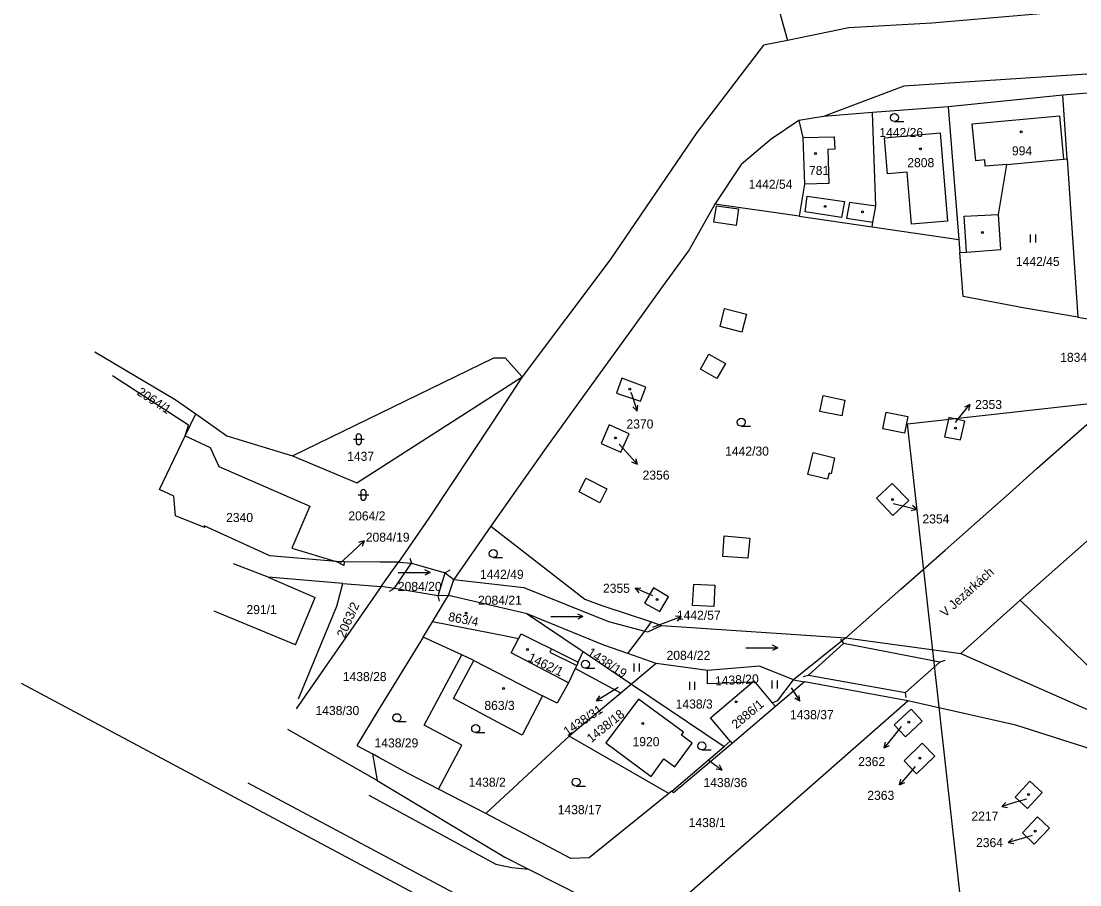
# Model space of a CAD drawing. Extents: x -793666 to -785424, y -1118958 to -1108761.
# Drawn here: x -792987.4 to -792788.6, y -1110324.4 to -1110162.1 of the extents above; entities that cross this region are included whole.
import ezdxf

# ---------------------------------------------------------------- set-up
doc = ezdxf.new("R2010")
doc.units = 0
for name, color, linetype in [('1_2000 - úřady', 7, 'Continuous'), ('Hranice parcel', 7, 'Continuous'), ('Parcelní čísla', 7, 'Continuous'), ('Pop  PČ popisy', 7, 'Continuous'), ('Vnitřní kresba', 7, 'Continuous'), ('Značky budov', 7, 'Continuous'), ('Značky kultur', 7, 'Continuous')]:
    doc.layers.add(name, color=color, linetype=linetype)

msp = doc.modelspace()

# ---------------------------------------------------------------- linework, layer by layer
at = {"layer": '1_2000 - úřady'}
msp.add_lwpolyline([(-792522.06, -1110204.41), (-792422.02, -1111099.6), (-792720.93, -1111133), (-792820.96, -1110237.81)], close=True, dxfattribs=at)
at = {"layer": 'Hranice parcel'}
for p, q in [((-792845.9, -1110157.04), (-792843.51, -1110165.75)), ((-792765.3, -1110173.93), (-792791.78, -1110176.05)), ((-792791.78, -1110176.05), (-792813.29, -1110178.21)), ((-792790.97, -1110188.03), (-792791.78, -1110176.05)), ((-792813.29, -1110178.21), (-792827.55, -1110179.32)), ((-792813.29, -1110178.21), (-792811.29, -1110203.16)), ((-792836.73, -1110180.03), (-792841.38, -1110180.79)), ((-792827.55, -1110179.32), (-792836.73, -1110180.03)), ((-792790.97, -1110188.03), (-792788.97, -1110217.76)), ((-792841.32, -1110198.79), (-792857.15, -1110196.49)), ((-792841.32, -1110198.79), (-792827.6, -1110200.79)), ((-792827.6, -1110200.79), (-792811.29, -1110203.16)), ((-792811.29, -1110203.16), (-792811.1, -1110205.6)), ((-792788.97, -1110217.76), (-792768.39, -1110221.23)), ((-792973.54, -1110224.23), (-792958.48, -1110233.18)), ((-792958.48, -1110233.18), (-792954.6, -1110235.91)), ((-792956.62, -1110240.06), (-792954.6, -1110235.91)), ((-792954.6, -1110235.91), (-792948.79, -1110240.01)), ((-792956.62, -1110240.06), (-792951.92, -1110242.23)), ((-792948.79, -1110240.01), (-792936.43, -1110243.76)), ((-792769.54, -1110244.05), (-792799.79, -1110270.88)), ((-792899.17, -1110257.02), (-792906.12, -1110267.05)), ((-792926.76, -1110263.67), (-792928.23, -1110263.66)), ((-792919.79, -1110268.32), (-792916.57, -1110263.77)), ((-792919.79, -1110268.32), (-792935.78, -1110291.3)), ((-792907.12, -1110270), (-792906.12, -1110267.05)), ((-792892.36, -1110273.46), (-792907.12, -1110270)), ((-792810.95, -1110280.9), (-792799.79, -1110270.88)), ((-792911.93, -1110277.84), (-792910.16, -1110274.96)), ((-792870.31, -1110276.7), (-792869.04, -1110275)), ((-792869.04, -1110275), (-792867.13, -1110275.64)), ((-792867.13, -1110275.64), (-792832.52, -1110277.99)), ((-792904.66, -1110281.18), (-792911.93, -1110277.84)), ((-792873.47, -1110280.93), (-792870.31, -1110276.7)), ((-792832.52, -1110277.99), (-792842.37, -1110285.86)), ((-792832.52, -1110277.99), (-792810.95, -1110280.9)), ((-792882.78, -1110282.53), (-792881.86, -1110280.55)), ((-792881.86, -1110280.55), (-792872.78, -1110286.68)), ((-792868.13, -1110282.78), (-792873.47, -1110280.93)), ((-792883.35, -1110283.75), (-792884.61, -1110286.45)), ((-792874.76, -1110288.34), (-792883.35, -1110283.75)), ((-792868.13, -1110282.78), (-792872.78, -1110286.68)), ((-792858.5, -1110284.12), (-792868.13, -1110282.78)), ((-792840.31, -1110286.24), (-792845.77, -1110290.89)), ((-792842.37, -1110285.86), (-792840.31, -1110286.24)), ((-792820.87, -1110289.8), (-792840.31, -1110286.24)), ((-792874.76, -1110288.34), (-792884.46, -1110296.46)), ((-792872.78, -1110286.68), (-792874.76, -1110288.34)), ((-792872.78, -1110286.68), (-792855.41, -1110298.4)), ((-792845.77, -1110290.89), (-792846.34, -1110290.21)), ((-792845.77, -1110290.89), (-792853.89, -1110297.81)), ((-792920.52, -1110304.75), (-792937.34, -1110295.19)), ((-792884.46, -1110296.46), (-792900.15, -1110310.99)), ((-792865.76, -1110307.22), (-792884.46, -1110296.46)), ((-792924.39, -1110298.18), (-792921.42, -1110299.79)), ((-792865.22, -1110306.76), (-792855.41, -1110298.4)), ((-792853.89, -1110297.81), (-792864.87, -1110307.09)), ((-792855.41, -1110298.4), (-792854.27, -1110297.36)), ((-792854.27, -1110297.36), (-792853.89, -1110297.81)), ((-792921.42, -1110299.79), (-792920.52, -1110304.75)), ((-792900.15, -1110310.99), (-792909.06, -1110306.37)), ((-792865.22, -1110306.76), (-792865.76, -1110307.22)), ((-792864.87, -1110307.09), (-792865.22, -1110306.76))]:
    msp.add_line(p, q, dxfattribs=at)
for points in [[(-792793.11, -1110160.53), (-792816.41, -1110162.52), (-792831.95, -1110163.4), (-792843.51, -1110165.75)], [(-792843.51, -1110165.75), (-792848, -1110166.66), (-792860.5, -1110183.08), (-792876.83, -1110207.04), (-792893.29, -1110228.94)], [(-792724.21, -1110167.98), (-792821.65, -1110174.35), (-792836.73, -1110180.03)], [(-792841.38, -1110180.79), (-792846.53, -1110184.28), (-792852.19, -1110189.06), (-792857.15, -1110196.49)], [(-792841.38, -1110180.79), (-792840.6, -1110183.99), (-792840.3, -1110192.79), (-792841.32, -1110198.79)], [(-792827.6, -1110200.79), (-792827.45, -1110199.93), (-792826.92, -1110196.88), (-792827.55, -1110179.32)], [(-792813.45, -1110199.69), (-792820.2, -1110200.26), (-792821.03, -1110190.53), (-792824.71, -1110190.8), (-792825.3, -1110184.04), (-792814.83, -1110183.14), (-792813.45, -1110199.69)], [(-792811.1, -1110205.6), (-792809.89, -1110205.52), (-792803.4, -1110205.05), (-792803.88, -1110198.43), (-792802.3, -1110189.05), (-792791.66, -1110188.09), (-792790.97, -1110188.03)], [(-792857.15, -1110196.49), (-792861.96, -1110205.07), (-792867.33, -1110212.5), (-792872.43, -1110219.57), (-792877.35, -1110226.4), (-792878.15, -1110227.5), (-792883.23, -1110234.55), (-792888.74, -1110242.19), (-792893.98, -1110249.64), (-792899.17, -1110257.02)], [(-792788.97, -1110217.76), (-792798.95, -1110216.07), (-792810.47, -1110213.88), (-792811.1, -1110205.6)], [(-792832.52, -1110277.99), (-792822.21, -1110268.85), (-792813.91, -1110261.49), (-792801.89, -1110250.87), (-792796.66, -1110246.15), (-792768.39, -1110221.23)], [(-792936.43, -1110243.76), (-792898.61, -1110225.41), (-792896.52, -1110225.36), (-792893.29, -1110228.94)], [(-792956.62, -1110240.06), (-792955.98, -1110238.02), (-792970.23, -1110228.78)], [(-792936.43, -1110243.76), (-792924.34, -1110248.84), (-792893.29, -1110228.94)], [(-792893.29, -1110228.94), (-792898.91, -1110237.46), (-792910.83, -1110255.53), (-792916.57, -1110263.77)], [(-792874.62, -1110229.22), (-792875.6, -1110231.99), (-792871.07, -1110233.51), (-792870.1, -1110230.91), (-792874.62, -1110229.22)], [(-792813.99, -1110240.21), (-792811, -1110240.77), (-792810.21, -1110237.29), (-792813.21, -1110236.61), (-792813.99, -1110240.21)], [(-792874.8, -1110243.12), (-792873.23, -1110239.68), (-792876.98, -1110237.97), (-792878.45, -1110241.45), (-792874.8, -1110243.12)], [(-792928.23, -1110263.66), (-792940.73, -1110262.6), (-792953.02, -1110256.95), (-792953, -1110257.24), (-792958.43, -1110255.07), (-792958.74, -1110251.34), (-792961.42, -1110250.11), (-792956.62, -1110240.06)], [(-792951.92, -1110242.23), (-792950.31, -1110245.78), (-792933.18, -1110253.25), (-792936.55, -1110261.13), (-792928.23, -1110263.66)], [(-792823.85, -1110248.99), (-792826.77, -1110251.75), (-792823.7, -1110254.99), (-792820.68, -1110252.18), (-792823.85, -1110248.99)], [(-792899.17, -1110257.02), (-792881.53, -1110270.73), (-792878.38, -1110271.88), (-792869.04, -1110275)], [(-792927.02, -1110267.74), (-792941.03, -1110266.61), (-792947.55, -1110264.05)], [(-792926.76, -1110263.67), (-792926.8, -1110264.36), (-792928.23, -1110263.66)], [(-792916.57, -1110263.77), (-792919.91, -1110263.74), (-792926.76, -1110263.67)], [(-792916.57, -1110263.77), (-792914.11, -1110263.94), (-792907.75, -1110265.75), (-792906.12, -1110267.05)], [(-792935.32, -1110289.46), (-792928.14, -1110272.02), (-792927.02, -1110267.74)], [(-792927.02, -1110267.74), (-792921.4, -1110268.19), (-792919.79, -1110268.32)], [(-792907.12, -1110270), (-792909.08, -1110270.11), (-792917.38, -1110268.7), (-792919.79, -1110268.32)], [(-792906.12, -1110267.05), (-792893, -1110268.51), (-792877.11, -1110274.91), (-792870.31, -1110276.7)], [(-792867.49, -1110273.06), (-792865.84, -1110270.25), (-792868.65, -1110268.61), (-792870.36, -1110271.49), (-792867.49, -1110273.06)], [(-792910.16, -1110274.96), (-792907.69, -1110270.93), (-792907.12, -1110270)], [(-792799.79, -1110270.88), (-792785.68, -1110284.61), (-792780.46, -1110289.67), (-792774.1, -1110287.81), (-792768.98, -1110283.36), (-792748.68, -1110294.88)], [(-792892.36, -1110273.46), (-792882.45, -1110280.15), (-792881.86, -1110280.55)], [(-792873.47, -1110280.93), (-792877.98, -1110279.37), (-792892.36, -1110273.46)], [(-792894.02, -1110278.16), (-792896.04, -1110277.71), (-792910.16, -1110274.96)], [(-792870.31, -1110276.7), (-792869.7, -1110276.86), (-792867.13, -1110275.64)], [(-792911.93, -1110277.84), (-792920.4, -1110291.66), (-792924.39, -1110298.18)], [(-792884.61, -1110286.45), (-792895.4, -1110280.77), (-792894.02, -1110278.16)], [(-792894.02, -1110278.16), (-792893.53, -1110277.23), (-792890.72, -1110278.62), (-792887.81, -1110280.05), (-792882.78, -1110282.53)], [(-792909.06, -1110306.37), (-792904.65, -1110298.12), (-792911.69, -1110294.36), (-792904.66, -1110281.18)], [(-792884.61, -1110286.45), (-792886.72, -1110290.26), (-792889.5, -1110288.84), (-792893.29, -1110296.28), (-792896.99, -1110294.3), (-792906.21, -1110289.36), (-792902.39, -1110282.23), (-792904.66, -1110281.18)], [(-792882.78, -1110282.53), (-792883.08, -1110283.17), (-792883.35, -1110283.75)], [(-792810.95, -1110280.9), (-792780.07, -1110294.56), (-792755.03, -1110302.83), (-792738.35, -1110319.04), (-792720.66, -1110333.41), (-792681.61, -1110364.96), (-792649.52, -1110392.89)], [(-792850.04, -1110286.28), (-792858.54, -1110286.62), (-792858.5, -1110284.12)], [(-792842.37, -1110285.86), (-792848.73, -1110283.28), (-792858.5, -1110284.12)], [(-792987.4, -1110286.52), (-792903.63, -1110331.24), (-792901.83, -1110335.69)], [(-792854.27, -1110297.36), (-792857.96, -1110292.98), (-792850.04, -1110286.28)], [(-792850.04, -1110286.28), (-792849.81, -1110286.08), (-792846.34, -1110290.21)], [(-792846.34, -1110290.21), (-792845.29, -1110289.77), (-792842.37, -1110285.86)], [(-792863.41, -1110296.26), (-792863, -1110295.7), (-792871.48, -1110289.47), (-792877.63, -1110297.71), (-792869.11, -1110304.01), (-792866.7, -1110300.73)], [(-792861.96, -1110336.71), (-792864.51, -1110333.18), (-792865.03, -1110328.55), (-792820.87, -1110289.8)], [(-792614.4, -1110416.41), (-792624.78, -1110416.77), (-792634.65, -1110411.27), (-792666.12, -1110385.5), (-792684.9, -1110369.28), (-792739.95, -1110324.15), (-792759.16, -1110307.61), (-792800.59, -1110294.35), (-792820.87, -1110289.8)], [(-792821.33, -1110296.58), (-792818.18, -1110293.63), (-792820.28, -1110291.38), (-792823.43, -1110294.34), (-792821.33, -1110296.58)], [(-792866.7, -1110300.73), (-792864.66, -1110302.23), (-792861.37, -1110297.76), (-792863.41, -1110296.26)], [(-792819.27, -1110303.52), (-792815.84, -1110300.19), (-792818.18, -1110297.78), (-792821.61, -1110301.11), (-792819.27, -1110303.52)], [(-792909.06, -1110306.37), (-792914.61, -1110303.49), (-792920.21, -1110300.45), (-792921.42, -1110299.79)], [(-792920.52, -1110304.75), (-792896.6, -1110319.19), (-792892.13, -1110321.45), (-792866.5, -1110334.41), (-792861.96, -1110336.71)], [(-792795.65, -1110307), (-792797.95, -1110304.89), (-792800.73, -1110307.93), (-792798.43, -1110310.03), (-792795.65, -1110307)], [(-792865.76, -1110307.22), (-792880.76, -1110319.28), (-792884.2, -1110319.45), (-792900.15, -1110310.99)], [(-792794.31, -1110313.72), (-792796.53, -1110311.62), (-792799.38, -1110314.63), (-792797.16, -1110316.73), (-792794.31, -1110313.72)]]:
    msp.add_lwpolyline(points, dxfattribs=at)
at = {"layer": 'Pop  PČ popisy'}
for p, q in [((-792872.92, -1110231.83), (-792872.68, -1110232.55)), ((-792872.68, -1110232.55), (-792871.75, -1110235.4)), ((-792871.75, -1110235.4), (-792872.54, -1110234.61)), ((-792871.75, -1110235.4), (-792871.59, -1110234.3)), ((-792811.14, -1110236.49), (-792809.25, -1110234.16)), ((-792809.25, -1110234.16), (-792810.27, -1110234.62)), ((-792809.25, -1110234.16), (-792809.49, -1110235.25)), ((-792811.96, -1110237.5), (-792811.14, -1110236.49)), ((-792875.08, -1110241.63), (-792873.69, -1110243.19)), ((-792873.69, -1110243.19), (-792871.68, -1110245.42)), ((-792871.68, -1110245.42), (-792871.98, -1110244.34)), ((-792871.68, -1110245.42), (-792872.72, -1110245.01)), ((-792823.62, -1110252.74), (-792822.06, -1110253.14)), ((-792822.06, -1110253.14), (-792819.15, -1110253.87)), ((-792819.15, -1110253.87), (-792820.24, -1110254.11)), ((-792819.15, -1110253.87), (-792820, -1110253.14)), ((-792925.18, -1110261.82), (-792922.98, -1110259.77)), ((-792922.98, -1110259.77), (-792924.06, -1110260.09)), ((-792922.98, -1110259.77), (-792923.38, -1110260.82)), ((-792927.41, -1110263.89), (-792925.18, -1110261.82)), ((-792872.12, -1110268.66), (-792871.01, -1110268.59)), ((-792869.36, -1110269.83), (-792872.12, -1110268.66)), ((-792872.12, -1110268.66), (-792871.4, -1110269.51)), ((-792868.75, -1110270.08), (-792869.36, -1110269.83)), ((-792866.25, -1110275.03), (-792863.43, -1110274)), ((-792863.43, -1110274), (-792864.54, -1110273.88)), ((-792863.43, -1110274), (-792864.2, -1110274.82)), ((-792868.77, -1110275.95), (-792866.25, -1110275.03)), ((-792876.79, -1110288.23), (-792879.33, -1110289.82)), ((-792875.31, -1110287.31), (-792876.79, -1110288.23)), ((-792842.78, -1110287.38), (-792841.15, -1110289.9)), ((-792879.33, -1110289.82), (-792878.75, -1110288.86)), ((-792879.33, -1110289.82), (-792878.22, -1110289.71)), ((-792841.15, -1110289.9), (-792842.11, -1110289.33)), ((-792841.15, -1110289.9), (-792841.27, -1110288.78)), ((-792823.47, -1110296.29), (-792825.32, -1110298.66)), ((-792822.17, -1110294.61), (-792823.47, -1110296.29)), ((-792825.32, -1110298.66), (-792825.1, -1110297.56)), ((-792825.32, -1110298.66), (-792824.31, -1110298.17)), ((-792858.17, -1110301.04), (-792855.77, -1110302.85)), ((-792855.77, -1110302.85), (-792856.27, -1110301.84)), ((-792819.5, -1110302.17), (-792820.51, -1110303.32)), ((-792855.77, -1110302.85), (-792856.87, -1110302.64)), ((-792820.51, -1110303.32), (-792822.48, -1110305.58)), ((-792822.48, -1110305.58), (-792822.2, -1110304.5)), ((-792822.48, -1110305.58), (-792821.44, -1110305.16)), ((-792798.63, -1110308.25), (-792800.4, -1110308.79)), ((-792800.4, -1110308.79), (-792803.27, -1110309.67)), ((-792803.27, -1110309.67), (-792802.46, -1110308.9)), ((-792803.27, -1110309.67), (-792802.17, -1110309.85)), ((-792799.19, -1110315.6), (-792802.08, -1110316.43)), ((-792802.08, -1110316.43), (-792801.25, -1110315.67)), ((-792802.08, -1110316.43), (-792800.97, -1110316.63)), ((-792797.52, -1110315.11), (-792799.19, -1110315.6))]:
    msp.add_line(p, q, dxfattribs=at)
at = {"layer": 'Vnitřní kresba'}
for p, q in [((-792808.83, -1110181.45), (-792792.4, -1110179.95)), ((-792792.4, -1110179.95), (-792791.66, -1110188.09)), ((-792808.1, -1110188.37), (-792808.83, -1110181.45)), ((-792840.6, -1110183.99), (-792834.75, -1110183.87)), ((-792834.75, -1110183.87), (-792834.58, -1110186.16)), ((-792834.58, -1110186.16), (-792835.89, -1110186.25)), ((-792835.89, -1110186.25), (-792835.7, -1110192.61)), ((-792806.46, -1110188.19), (-792808.1, -1110188.37)), ((-792806.34, -1110189.41), (-792806.46, -1110188.19)), ((-792802.3, -1110189.05), (-792806.34, -1110189.41)), ((-792835.7, -1110192.61), (-792840.3, -1110192.79)), ((-792840.2, -1110197.95), (-792839.77, -1110194.99)), ((-792839.77, -1110194.99), (-792832.76, -1110196.02)), ((-792857.35, -1110199.89), (-792856.8, -1110196.81)), ((-792856.8, -1110196.81), (-792852.66, -1110197.4)), ((-792832.76, -1110196.02), (-792833.34, -1110199.02)), ((-792831.86, -1110196.19), (-792832.4, -1110199.16)), ((-792826.92, -1110196.88), (-792831.86, -1110196.19)), ((-792852.66, -1110197.4), (-792853.13, -1110200.52)), ((-792833.34, -1110199.02), (-792840.2, -1110197.95)), ((-792810.29, -1110198.78), (-792803.88, -1110198.43)), ((-792809.89, -1110205.52), (-792810.29, -1110198.78)), ((-792853.13, -1110200.52), (-792857.35, -1110199.89)), ((-792832.4, -1110199.16), (-792827.45, -1110199.93)), ((-792856.16, -1110219.49), (-792855.29, -1110216.11)), ((-792855.29, -1110216.11), (-792851.2, -1110217.2)), ((-792851.2, -1110217.2), (-792852.08, -1110220.56)), ((-792852.08, -1110220.56), (-792856.16, -1110219.49)), ((-792859.83, -1110227.54), (-792858.25, -1110224.71)), ((-792858.25, -1110224.71), (-792855.15, -1110226.43)), ((-792855.15, -1110226.43), (-792856.73, -1110229.27)), ((-792856.73, -1110229.27), (-792859.83, -1110227.54)), ((-792837.43, -1110235.48), (-792836.76, -1110232.44)), ((-792836.76, -1110232.44), (-792832.7, -1110233.35)), ((-792832.7, -1110233.35), (-792833.26, -1110236.25)), ((-792833.26, -1110236.25), (-792837.43, -1110235.48)), ((-792825.57, -1110238.69), (-792824.93, -1110235.56)), ((-792824.93, -1110235.56), (-792820.88, -1110236.41)), ((-792820.88, -1110236.41), (-792821.5, -1110239.52)), ((-792821.5, -1110239.52), (-792825.57, -1110238.69)), ((-792839.7, -1110247.27), (-792838.69, -1110243.18)), ((-792838.69, -1110243.18), (-792834.64, -1110244.14)), ((-792834.64, -1110244.14), (-792835.31, -1110247.16)), ((-792882.6, -1110250.56), (-792881.34, -1110248.01)), ((-792881.34, -1110248.01), (-792877.43, -1110250)), ((-792835.97, -1110248.19), (-792839.7, -1110247.27)), ((-792835.69, -1110247.06), (-792835.97, -1110248.19)), ((-792835.31, -1110247.16), (-792835.69, -1110247.06)), ((-792878.75, -1110252.61), (-792882.6, -1110250.56)), ((-792877.43, -1110250), (-792878.75, -1110252.61)), ((-792855.65, -1110262.71), (-792855.41, -1110258.83)), ((-792855.41, -1110258.83), (-792850.59, -1110259.23)), ((-792850.59, -1110259.23), (-792850.91, -1110263.04)), ((-792850.91, -1110263.04), (-792855.65, -1110262.71)), ((-792917.38, -1110268.7), (-792914.11, -1110263.94)), ((-792914.42, -1110262.99), (-792914.11, -1110263.94)), ((-792941.03, -1110266.61), (-792932.22, -1110270.38)), ((-792909.08, -1110270.11), (-792907.75, -1110265.75)), ((-792906.88, -1110265.27), (-792907.75, -1110265.75)), ((-792918.23, -1110269.23), (-792917.38, -1110268.7)), ((-792861.34, -1110271.93), (-792861.09, -1110267.89)), ((-792861.09, -1110267.89), (-792857.12, -1110268.09)), ((-792857.12, -1110268.09), (-792857.32, -1110272.1)), ((-792935.89, -1110279.29), (-792932.22, -1110270.38)), ((-792908.84, -1110271.08), (-792909.08, -1110270.11)), ((-792857.32, -1110272.1), (-792861.34, -1110271.93)), ((-792935.89, -1110279.29), (-792951.18, -1110272.99)), ((-792833.52, -1110278.2), (-792833, -1110279.06)), ((-792887.81, -1110280.05), (-792888.12, -1110280.67)), ((-792833, -1110279.06), (-792839.55, -1110285.01)), ((-792814.88, -1110282.54), (-792833, -1110279.06)), ((-792902.39, -1110282.23), (-792889.5, -1110288.84)), ((-792888.12, -1110280.67), (-792883.08, -1110283.17)), ((-792821.32, -1110288.22), (-792814.88, -1110282.54)), ((-792813.93, -1110282.22), (-792814.88, -1110282.54)), ((-792840.53, -1110285.22), (-792839.55, -1110285.01)), ((-792839.55, -1110285.01), (-792821.32, -1110288.22)), ((-792821.18, -1110289.21), (-792821.32, -1110288.22)), ((-792944.81, -1110305.21), (-792903.48, -1110327.29)), ((-792922.09, -1110307.54), (-792898.28, -1110320.5)), ((-792898.28, -1110320.5), (-792895.24, -1110321.1)), ((-792895.24, -1110321.1), (-792892.13, -1110321.45))]:
    msp.add_line(p, q, dxfattribs=at)
at = {"layer": 'Značky budov'}
for centre in [(-792799.59, -1110182.93), (-792838.22, -1110187.01), (-792818.54, -1110186.11), (-792836.4, -1110196.93), (-792829.4, -1110197.95), (-792806.89, -1110201.86), (-792873.12, -1110231.28), (-792811.93, -1110238.61), (-792875.8, -1110240.43), (-792823.75, -1110251.99), (-792867.99, -1110270.79), (-792903.86, -1110273.34), (-792892.32, -1110280.17), (-792896.81, -1110287.5), (-792853.11, -1110289.97), (-792870.68, -1110294.08), (-792820.69, -1110293.81), (-792818.61, -1110300.58), (-792798.22, -1110307.39), (-792796.95, -1110314.29)]:
    msp.add_circle(centre, 0.175, dxfattribs=at)
at = {"layer": 'Značky kultur'}
for p, q in [((-792823.41, -1110181), (-792821.66, -1110181)), ((-792797.88, -1110203.74), (-792797.88, -1110202.24)), ((-792796.88, -1110203.74), (-792796.88, -1110202.24)), ((-792852.17, -1110238.22), (-792850.42, -1110238.22)), ((-792925.01, -1110240.68), (-792923.01, -1110240.68)), ((-792924.51, -1110240.18), (-792924.51, -1110241.18)), ((-792923.51, -1110241.18), (-792923.51, -1110240.18)), ((-792923.63, -1110250.63), (-792923.63, -1110251.63)), ((-792922.63, -1110251.63), (-792922.63, -1110250.63)), ((-792924.13, -1110251.13), (-792922.13, -1110251.13)), ((-792898.75, -1110262.89), (-792897, -1110262.89)), ((-792916.61, -1110265.68), (-792910.61, -1110265.68)), ((-792910.61, -1110265.68), (-792911.59, -1110265.18)), ((-792910.61, -1110265.68), (-792911.59, -1110266.18)), ((-792887.91, -1110274), (-792881.91, -1110274)), ((-792881.91, -1110274), (-792882.89, -1110273.5)), ((-792881.91, -1110274), (-792882.89, -1110274.5)), ((-792851.3, -1110279.84), (-792845.3, -1110279.84)), ((-792845.3, -1110279.84), (-792846.28, -1110279.34)), ((-792845.3, -1110279.84), (-792846.28, -1110280.34)), ((-792881.44, -1110283.69), (-792879.69, -1110283.69)), ((-792872.3, -1110284.28), (-792872.3, -1110282.78)), ((-792871.3, -1110284.28), (-792871.3, -1110282.78)), ((-792861.86, -1110287.77), (-792861.86, -1110286.27)), ((-792860.86, -1110287.77), (-792860.86, -1110286.27)), ((-792846.36, -1110287.47), (-792846.36, -1110285.97)), ((-792845.36, -1110287.47), (-792845.36, -1110285.97)), ((-792916.83, -1110293.72), (-792915.08, -1110293.72)), ((-792902.05, -1110295.76), (-792900.3, -1110295.76)), ((-792859.57, -1110299.03), (-792857.82, -1110299.03)), ((-792883.19, -1110305.83), (-792881.44, -1110305.83))]:
    msp.add_line(p, q, dxfattribs=at)
for centre in [(-792823.41, -1110180.25), (-792852.17, -1110237.47), (-792898.75, -1110262.14), (-792881.44, -1110282.94), (-792916.83, -1110292.97), (-792902.05, -1110295.01), (-792859.57, -1110298.28), (-792883.19, -1110305.08)]:
    msp.add_circle(centre, 0.75, dxfattribs=at)
for centre, start, end in [((-792924.01, -1110240.18), 0, 180), ((-792924.01, -1110241.18), 180, 359.9879), ((-792923.13, -1110250.63), 0, 180), ((-792923.13, -1110251.63), 180, 359.9879)]:
    msp.add_arc(centre, 0.5, start, end, dxfattribs=at)

# ---------------------------------------------------------------- texts
at = {"layer": 'Parcelní čísla'}
for s, p in [('1442/26', (-792826.24, -1110183.91)), ('994', (-792801.34, -1110187.35)), ('2808', (-792820.99, -1110189.57)), ('781', (-792839.45, -1110191.04)), ('1442/54', (-792850.78, -1110193.63)), ('1442/45', (-792800.6, -1110208.14)), ('1834', (-792792.28, -1110226.14)), ('2353', (-792808.26, -1110235)), ('2370', (-792873.73, -1110238.66)), ('1442/30', (-792855.2, -1110243.76)), ('1437', (-792926.18, -1110244.73)), ('2356', (-792870.7, -1110248.26)), ('2340', (-792948.91, -1110256.22)), ('2064/2', (-792925.95, -1110255.92)), ('2354', (-792818.15, -1110256.49)), ('2084/19', (-792922.68, -1110259.92)), ('1442/49', (-792901.25, -1110266.9)), ('2084/20', (-792916.66, -1110269.17)), ('2355', (-792878.14, -1110269.52)), ('2084/21', (-792901.6, -1110271.76)), ('291/1', (-792945.09, -1110273.52)), ('1442/57', (-792864.26, -1110274.58)), ('2084/22', (-792866.2, -1110282.11)), ('1438/28', (-792927, -1110286.11)), ('863/3', (-792900.41, -1110291.52)), ('1438/3', (-792864.49, -1110291.26)), ('1438/30', (-792932.13, -1110292.48)), ('1438/37', (-792843.03, -1110293.26)), ('1438/29', (-792921.04, -1110298.56)), ('1920', (-792872.59, -1110298.33)), ('2362', (-792830.21, -1110302.07)), ('1438/2', (-792903.36, -1110305.94)), ('1438/36', (-792859.26, -1110306.01)), ('2363', (-792828.5, -1110308.41)), ('1438/17', (-792886.64, -1110311.1)), ('1438/1', (-792862.04, -1110313.53)), ('2217', (-792808.94, -1110312.31)), ('2364', (-792808.08, -1110317.29))]:
    msp.add_text(s, height=1.7, dxfattribs=at).set_placement(p)
for s, rotation, p in [('2064/1', 327, (-792965.79, -1110232.21)), ('2063/2', 66, (-792926.66, -1110278.11)), ('863/4', 349, (-792907.3, -1110274.77)), ('1438/19', 327, (-792881.25, -1110281.12)), ('1462/1', 334, (-792892.38, -1110282.23)), ('1438/20', 3, (-792857.05, -1110286.93)), ('2886/1', 40, (-792853.1, -1110295.18)), ('1438/31', 34, (-792884.84, -1110296.46)), ('1438/18', 39, (-792880.33, -1110297.78))]:
    msp.add_text(s, height=1.7, rotation=rotation, dxfattribs=at).set_placement(p)
at = {"layer": 'Pop  PČ popisy'}
msp.add_text('V Jezárkách', height=1.7, rotation=42, dxfattribs=at).set_placement((-792813.87, -1110274.2))

doc.saveas('drawing.dxf')
